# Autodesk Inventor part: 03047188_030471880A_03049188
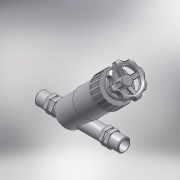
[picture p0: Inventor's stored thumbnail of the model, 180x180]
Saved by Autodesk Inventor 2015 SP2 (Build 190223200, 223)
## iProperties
Created: 2017-05
Part Number: 03047188_030471880A_03049188
Material: Generic
Description: PLASSON ANGLE SEAT VALVE 1.1/4"-1.1/4"
Document SubType Name: Modeling
Designer: KIM
Mass: 184.302 g
Surface Area: 375.869 cm^2
Volume: 184.302 cm^3
Density: 1 g/cm^3
Appearance: Default
Author: KIM
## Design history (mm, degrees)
derived "03047.ipt"
feature "Solid1::03047.ipt"
tag "TaggingFeature1"
body "Solid1"
other parameters: "d0" = 225, "d1" = 47.803, "d3" = 38.2424, "d4" = 22, "d5" = 22, "d6" = 22.5, "d8" = 2.25, "d12" = 0, "d14" = -11.25, "d15" = 4.5, "d16" = 0, "d17" = 61.479, "d19" = 195.615, "d20" = 74.52, "d21" = 135 deg, "d22" = 79.1775, "d23" = 37.26, "d24" = 88.4925, "d25" = 22.356, "d26" = 90 deg, "d27" = 65.205, "d28" = 70 deg, "d29" = 27.945, "d30" = 22.356, "d31" = 27.945, "d32" = 93.15, "d33" = 65.205, "d34" = 135 deg, "d35" = 2, "d36" = 186.3, "d39" = 78.75, "d40" = 2.07, "d42" = 2, "d43" = 6.21, "d44" = 6.21, "d46" = 0, "d48" = 360 deg, "d50" = 1.035, "d51" = 1.035, "d53" = 360 deg, "d69" = 79.1775, "d70" = 6.21, "d71" = 6.21, "d72" = 12.42, "d74" = 0, "d75" = 1.035, "d77" = 360 deg, "d80" = 85.83773, "d81" = 8.28, "d82" = 4.14, "d83" = 33.534, "d84" = 0, "d86" = 360 deg, "d88" = 2.07, "d89" = 7.452, "d90" = 1.035, "d91" = 207, "H_" = 225, "R_" = 47.803, "l_2" = 22, "A_" = 207, "d13" = 22.5, "d67" = 93.15, "d68" = 65.205, "d79" = 88.4925
